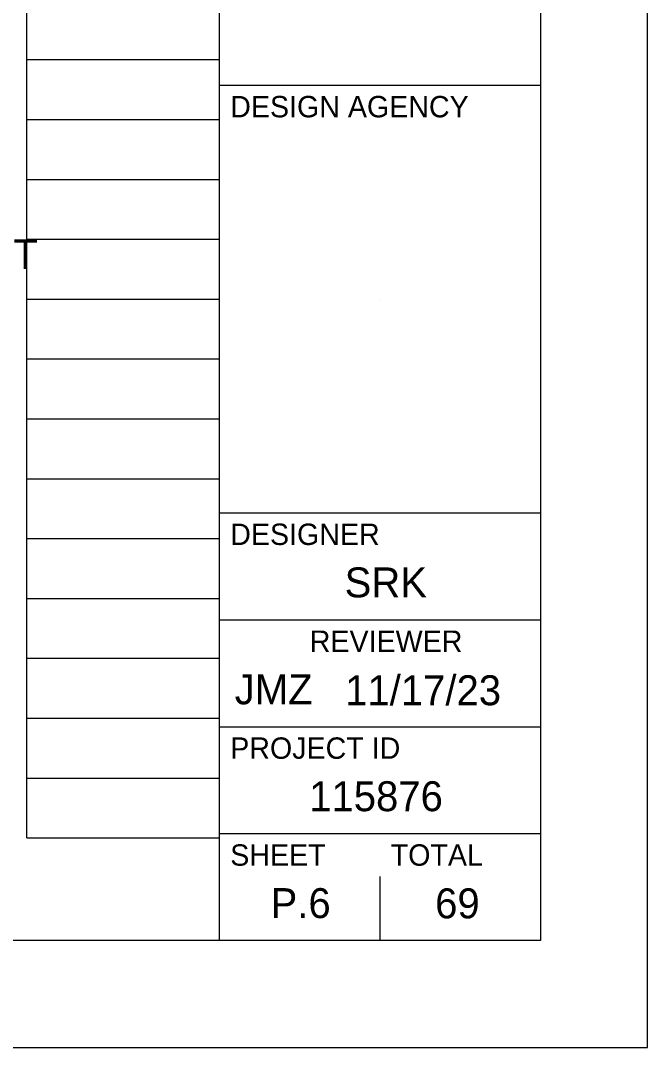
# Model space of a CAD drawing. Extents: x 0 to 37.9, y 0 to 22.
# Drawn here: x 31.07 to 34, y 0 to 4.803 of the extents above; entities that cross this region are included whole.
import ezdxf

# ---------------------------------------------------------------- set-up
doc = ezdxf.new("R2010")
doc.units = 0
for name, color, linetype in [('SH_Border', 7, 'Continuous'), ('SH_Cut_Line', 7, 'Continuous'), ('SH_Data', 7, 'Continuous'), ('SH_Text', 7, 'Continuous')]:
    doc.layers.add(name, color=color, linetype=linetype)

msp = doc.modelspace()

# ---------------------------------------------------------------- linework, layer by layer
at = {"layer": 'SH_Border'}
for p, q in [((32, 0.5), (32, 21.5)), ((32, 4.5), (33.5, 4.5)), ((32, 2.5), (33.5, 2.5)), ((32, 2), (33.5, 2)), ((32, 1.5), (33.5, 1.5)), ((32, 1), (33.5, 1))]:
    msp.add_line(p, q, dxfattribs=at)
msp.add_lwpolyline([(1.5, 21.5), (33.5, 21.5), (33.5, 0.5), (1.5, 0.5)], close=True, dxfattribs=at)
at = {"layer": 'SH_Cut_Line'}
msp.add_lwpolyline([(0, 0), (34, 0), (34, 22), (0, 22)], close=True, dxfattribs=at)
at = {"layer": 'SH_Data'}
for p, q in [((31.1, 0.98), (31.1, 21.14)), ((32, 0.98), (32, 21.14)), ((31.1, 4.62), (32, 4.62)), ((31.1, 4.34), (32, 4.34)), ((31.1, 4.06), (32, 4.06)), ((31.1, 3.78), (32, 3.78)), ((31.1, 3.5), (32, 3.5)), ((32.75, 3.5), (32.75, 3.5)), ((31.1, 3.22), (32, 3.22)), ((31.1, 2.94), (32, 2.94)), ((31.1, 2.66), (32, 2.66)), ((31.1, 2.38), (32, 2.38)), ((31.1, 2.1), (32, 2.1)), ((31.1, 1.82), (32, 1.82)), ((31.1, 1.54), (32, 1.54)), ((31.1, 1.26), (32, 1.26)), ((31.1, 0.98), (32, 0.98)), ((32.75, 0.5), (32.75, 0.8)), ((32.375, 0.675), (32.375, 0.675))]:
    msp.add_line(p, q, dxfattribs=at)

# ---------------------------------------------------------------- texts
for s, height, p in [('DESIGN AGENCY', 0.1, (32.05, 4.35)), ('DESIGNER', 0.1, (32.05, 2.35)), ('SRK', 0.14, (32.5847, 2.105)), ('REVIEWER', 0.1, (32.4218, 1.85)), ('JMZ', 0.14, (32.0712, 1.605)), ('11/17/23', 0.14, (32.5871, 1.6006)), ('PROJECT ID', 0.1, (32.05, 1.35)), ('115876', 0.14, (32.4191, 1.105)), ('SHEET', 0.1, (32.05, 0.85)), ('TOTAL', 0.1, (32.8, 0.85)), ('P.6', 0.14, (32.2386, 0.605)), ('69', 0.14, (33.0077, 0.604))]:
    msp.add_text(s, height=height, dxfattribs=at).set_placement(p)
at = {"layer": 'SH_Text'}
msp.add_text('BENDS OR BRANCHES IS INCLUDED FOR PAYMENT IN THE PERTINENT', height=0.14, dxfattribs=at).set_placement((24.66, 3.64))

doc.saveas('drawing.dxf')
